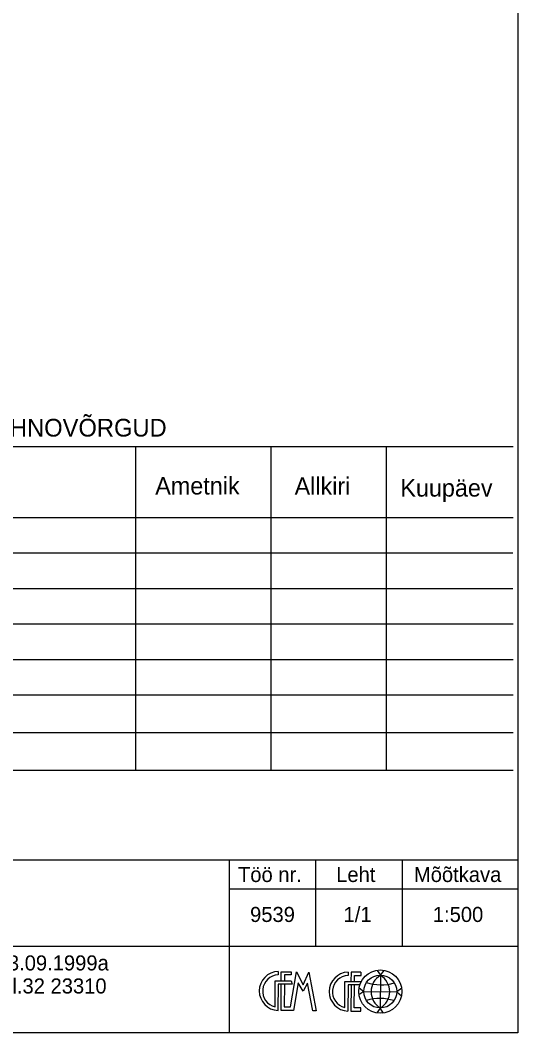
# Model space of a CAD drawing. Extents: x 714279 to 714471, y 6589851 to 6590083.
# Drawn here: x 714438.1 to 714471.1, y 6589929.1 to 6589996.4 of the extents above; entities that cross this region are included whole.
import ezdxf

# ---------------------------------------------------------------- set-up
doc = ezdxf.new("R2010")
doc.units = 0
doc.layers.add('VORMISTUS', color=7, linetype='Continuous')

msp = doc.modelspace()

# ---------------------------------------------------------------- linework, layer by layer
at = {"layer": 'VORMISTUS'}
for p, q in [((714406.062, 6589968.063), (714470.812, 6589968.063)), ((714445.772, 6589968.063), (714445.772, 6589946.573)), ((714454.732, 6589968.063), (714454.732, 6589946.573)), ((714462.392, 6589968.063), (714462.392, 6589946.573)), ((714406.042, 6589963.353), (714470.812, 6589963.353)), ((714406.042, 6589960.993), (714470.792, 6589960.993)), ((714406.042, 6589958.643), (714470.792, 6589958.643)), ((714406.062, 6589956.283), (714470.812, 6589956.283)), ((714406.062, 6589953.923), (714470.812, 6589953.923)), ((714406.062, 6589951.573), (714470.812, 6589951.573)), ((714406.062, 6589949.073), (714470.812, 6589949.073)), ((714406.062, 6589946.573), (714470.812, 6589946.573)), ((714452.004, 6589929.143), (714452.004, 6589940.613)), ((714452.004, 6589929.143), (714452.004, 6589940.613)), ((714457.734, 6589934.873), (714457.734, 6589940.613)), ((714457.734, 6589934.873), (714457.734, 6589940.613)), ((714463.474, 6589934.873), (714463.474, 6589940.613)), ((714463.474, 6589934.873), (714463.474, 6589940.613)), ((714452.002, 6589938.703), (714471.122, 6589938.703)), ((714471.122, 6589934.873), (714396.812, 6589934.873)), ((714471.122, 6589934.873), (714400.362, 6589934.873)), ((714455.234, 6589933.213), (714455.234, 6589932.983)), ((714462.014, 6589932.953), (714462.004, 6589930.783)), ((714455.224, 6589932.363), (714455.214, 6589930.613)), ((714455.224, 6589932.563), (714455.224, 6589932.563)), ((714460.634, 6589932.323), (714459.864, 6589932.333)), ((714460.912, 6589931.873), (714463.092, 6589931.863))]:
    msp.add_line(p, q, dxfattribs=at)
for points in [[(714471.122, 6589929.143), (714278.622, 6589929.143), (714278.622, 6590071.643), (714471.122, 6590071.643), (714471.122, 6589929.143)], [(714455.434, 6589932.583), (714455.434, 6589933.193), (714456.094, 6589933.193), (714456.094, 6589932.993), (714455.654, 6589932.983), (714455.654, 6589932.593)], [(714455.652, 6589932.363), (714455.632, 6589930.853), (714456.052, 6589930.853), (714456.442, 6589933.183), (714456.882, 6589932.333), (714457.262, 6589933.173), (714457.742, 6589930.603), (714457.522, 6589930.603), (714457.172, 6589932.433), (714456.882, 6589931.893), (714456.552, 6589932.453), (714456.242, 6589930.613)], [(714459.864, 6589933.163), (714459.864, 6589932.933)], [(714460.722, 6589933.163), (714460.062, 6589933.163), (714460.052, 6589932.553)], [(714460.284, 6589932.533), (714460.284, 6589932.953), (714460.724, 6589932.953), (714460.724, 6589933.163)], [(714461.792, 6589933.283), (714462.012, 6589932.963), (714462.252, 6589933.283)], [(714455.022, 6589930.853), (714455.022, 6589932.583), (714456.082, 6589932.583), (714456.162, 6589932.363), (714455.222, 6589932.363)], [(714456.242, 6589930.613), (714455.422, 6589930.613), (714455.432, 6589932.363)], [(714459.652, 6589930.823), (714459.652, 6589932.543), (714460.702, 6589932.543), (714460.722, 6589932.523)], [(714459.864, 6589932.333), (714459.854, 6589930.573)], [(714460.062, 6589932.323), (714460.052, 6589930.583), (714460.702, 6589930.573), (714460.712, 6589930.803), (714460.272, 6589930.803), (714460.282, 6589932.323)], [(714460.592, 6589932.123), (714460.912, 6589931.883), (714460.582, 6589931.653)], [(714463.422, 6589932.093), (714463.092, 6589931.863), (714463.412, 6589931.593)], [(714462.212, 6589930.453), (714462.002, 6589930.783), (714461.772, 6589930.463)]]:
    msp.add_lwpolyline(points, dxfattribs=at)
msp.add_lwpolyline([(714471.122, 6589929.143), (714396.812, 6589929.143), (714396.812, 6589940.613), (714471.122, 6589940.613)], close=True, dxfattribs=at)
for centre, radius in [((714462.004, 6589931.875), 1.434), ((714462.004, 6589931.88), 1.093)]:
    msp.add_circle(centre, radius, dxfattribs=at)
for centre, radius, start, end in [((714455.269, 6589931.916), 1.297, 91.77609, 267.7102), ((714455.278, 6589931.906), 1.08, 92.68702, 256.13029), ((714459.906, 6589931.873), 1.295, 91.95762, 267.78487), ((714459.903, 6589931.864), 1.078, 92.14875, 256.283), ((714462.653, 6589931.868), 1.259, 120.73712, 238.98643), ((714461.364, 6589931.87), 1.261, 300.51052, 58.93792), ((714462.043, 6589935.384), 3.061, 251.89399, 286.80305), ((714461.983, 6589928.428), 2.992, 72.0135, 107.3275)]:
    msp.add_arc(centre, radius, start, end, dxfattribs=at)

# ---------------------------------------------------------------- texts
for s, height, rotation, p in [('KOOSKÕLASTATUD  OLEMASOLEVAD TEHNOVÕRGUD ', 1.17642, 0.01, (714406.134, 6589968.713)), ('Ametnik', 1.159, 0.01, (714447.071, 6589964.873)), ('Allkiri', 1.159, 0.01, (714456.317, 6589964.853)), ('Kuupäev', 1.159, 0.01, (714463.334, 6589964.733)), ('Töö nr.', 1, 360, (714452.561, 6589939.149)), ('Leht', 1, 360, (714459.077, 6589939.149)), ('Mõõtkava ', 1, 360, (714464.235, 6589939.149)), ('1/1', 1, 360, (714459.565, 6589936.496)), ('9539', 1, 360, (714453.363, 6589936.496)), ('1:500', 1, 360, (714465.489, 6589936.496)), ('OÜ Gem-Geo  397 MA 23.09.1999a', 1, 360, (714422.58, 6589933.278)), ('Rakvere Lai tn 14-18    tel.32 23310', 1, 360, (714422.58, 6589931.748))]:
    msp.add_text(s, height=height, rotation=rotation, dxfattribs=at).set_placement(p)

doc.saveas('drawing.dxf')
